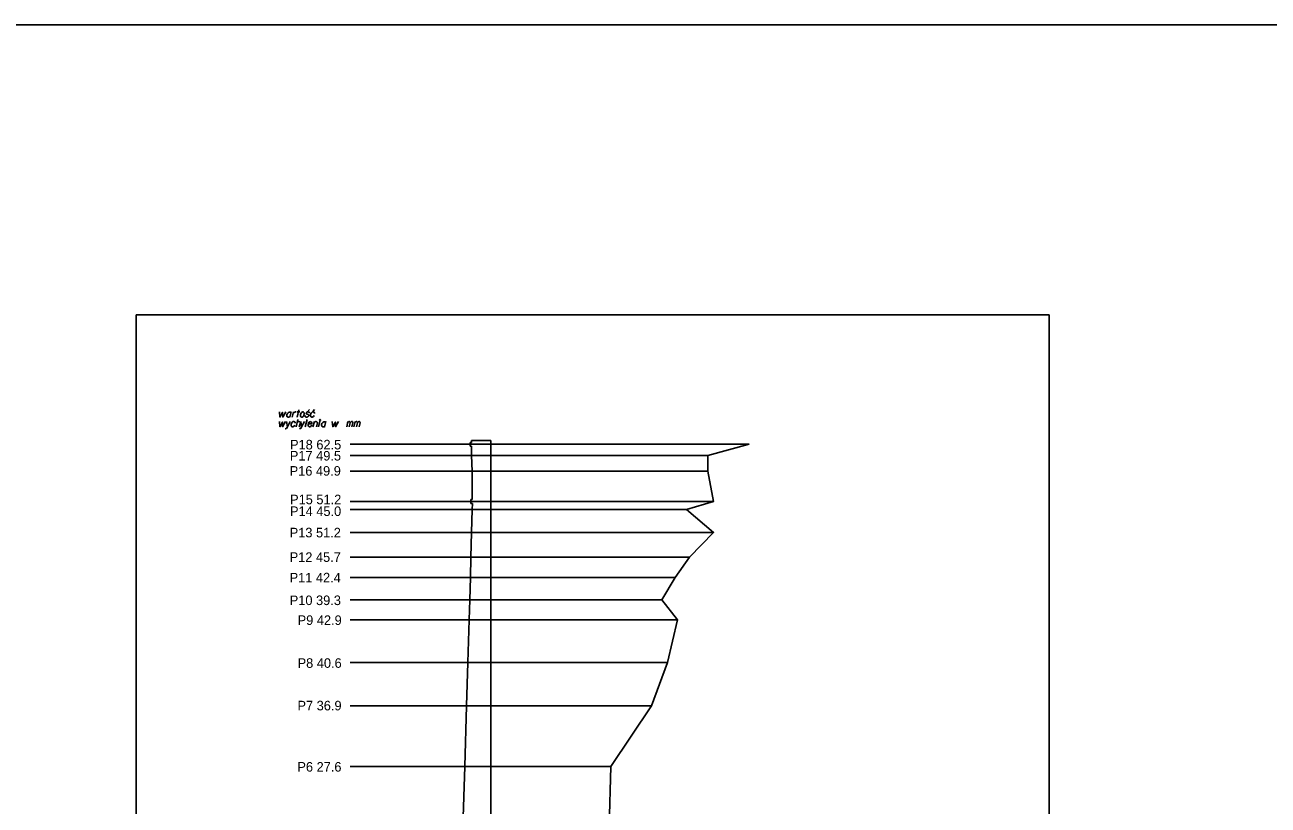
# Model space of a CAD drawing. Extents: x 138 to 264, y -75 to 121.
# Drawn here: x 166.54 to 195.15, y 20.71 to 38.66 of the extents above; entities that cross this region are included whole.
import ezdxf

# ---------------------------------------------------------------- set-up
doc = ezdxf.new("R2010")
doc.units = 0
for name, color, linetype in [('15 listopad 2008', 7, 'Continuous'), ('Ramka do drukowania', 7, 'Continuous'), ('Standart wykresów', 7, 'Continuous'), ('Wykresy 4 maj 2008', 7, 'Continuous')]:
    doc.layers.add(name, color=color, linetype=linetype)

msp = doc.modelspace()

# ---------------------------------------------------------------- linework, layer by layer
at = {"layer": '15 listopad 2008'}
msp.add_lwpolyline([(137.936, 38.661), (264.389, 38.661), (264.389, -75.347), (137.936, -75.347)], close=True, dxfattribs=at)
msp.add_lwpolyline([(177.265, 13.297), (177.835, 14.742), (178.265, 16.118), (178.825, 17.485), (179.085, 18.843), (179.985, 20.202), (180.025, 21.593), (180.955, 22.995), (181.325, 23.989), (181.555, 24.969), (181.195, 25.428), (181.505, 25.945), (181.835, 26.413), (182.385, 26.981), (181.765, 27.507), (182.385, 27.694), (182.255, 28.392), (182.255, 28.755), (183.205, 29.012)], dxfattribs=at)
at = {"layer": 'Ramka do drukowania'}
for p, q in [((169.105, 2.285), (169.105, 31.985)), ((169.105, 31.985), (190.105, 31.985)), ((190.105, 2.285), (190.105, 31.985))]:
    msp.add_line(p, q, dxfattribs=at)
at = {"layer": 'Standart wykresów'}
for p, q in [((177.265, 29.011), (174.028, 29.011)), ((176.783, 29.053), (176.783, 29.011)), ((176.82, 29.053), (176.783, 29.053)), ((176.783, 29.011), (176.783, 28.969)), ((176.82, 28.969), (176.783, 28.969)), ((176.82, 29.095), (176.82, 29.053)), ((176.82, 29.095), (177.265, 29.095)), ((176.82, 28.755), (176.82, 28.969)), ((177.265, 9.011), (177.265, 29.095)), ((177.265, 28.755), (174.028, 28.755)), ((176.835, 28.392), (176.82, 28.755)), ((177.265, 28.392), (174.028, 28.392)), ((176.835, 28.392), (176.835, 27.738)), ((177.265, 27.694), (174.028, 27.694)), ((177.265, 27.507), (174.028, 27.507)), ((176.805, 27.738), (176.805, 27.694)), ((176.805, 27.738), (176.835, 27.738)), ((176.805, 27.694), (176.805, 27.65)), ((176.839, 27.65), (176.805, 27.65)), ((176.82, 26.981), (176.835, 27.507)), ((176.835, 27.507), (176.839, 27.65)), ((177.265, 26.981), (174.028, 26.981)), ((176.805, 26.413), (176.82, 26.981)), ((177.265, 26.413), (174.028, 26.413)), ((176.79, 25.945), (176.805, 26.413)), ((177.265, 25.945), (174.028, 25.945)), ((176.778, 25.428), (176.79, 25.945)), ((177.265, 25.428), (174.028, 25.428)), ((176.76, 24.969), (176.778, 25.428)), ((177.265, 24.969), (174.028, 24.969)), ((176.733, 23.989), (176.76, 24.969)), ((177.265, 23.989), (174.028, 23.989)), ((176.703, 22.995), (176.733, 23.989)), ((177.265, 22.995), (174.028, 22.995)), ((176.663, 21.593), (176.703, 22.995)), ((177.265, 21.593), (174.028, 21.593)), ((176.618, 20.202), (176.663, 21.593))]:
    msp.add_line(p, q, dxfattribs=at)
for points in [[(172.399, 29.754), (172.409, 29.635), (172.472, 29.744), (172.473, 29.635), (172.543, 29.757)], [(172.663, 29.745), (172.654, 29.751), (172.632, 29.751), (172.618, 29.749), (172.595, 29.736), (172.575, 29.712), (172.566, 29.687), (172.565, 29.674), (172.566, 29.664), (172.57, 29.655), (172.578, 29.644), (172.587, 29.638), (172.601, 29.635), (172.612, 29.636), (172.622, 29.638), (172.637, 29.645)], [(172.666, 29.755), (172.634, 29.635)], [(172.688, 29.635), (172.721, 29.759)], [(172.713, 29.729), (172.719, 29.734), (172.734, 29.745), (172.749, 29.751), (172.761, 29.755), (172.779, 29.759)], [(172.802, 29.635), (172.845, 29.801)], [(172.802, 29.755), (172.864, 29.755)], [(172.934, 29.755), (172.943, 29.755), (172.953, 29.75), (172.964, 29.736), (172.965, 29.729), (172.966, 29.723), (172.966, 29.717), (172.966, 29.698), (172.963, 29.685), (172.956, 29.669), (172.948, 29.656), (172.935, 29.644), (172.923, 29.635), (172.904, 29.635), (172.896, 29.638), (172.888, 29.644), (172.884, 29.651), (172.879, 29.666), (172.879, 29.69), (172.881, 29.698), (172.887, 29.715), (172.892, 29.724), (172.894, 29.729), (172.908, 29.744), (172.921, 29.751), (172.934, 29.755)], [(173.089, 29.736), (173.086, 29.745), (173.076, 29.751), (173.069, 29.754), (173.057, 29.755), (173.046, 29.754), (173.031, 29.746), (173.02, 29.736), (173.016, 29.727), (173.015, 29.716), (173.017, 29.71), (173.023, 29.706), (173.025, 29.704), (173.033, 29.702), (173.042, 29.7), (173.055, 29.698), (173.063, 29.695), (173.07, 29.687), (173.072, 29.678), (173.071, 29.666), (173.066, 29.656), (173.055, 29.644), (173.046, 29.639), (173.036, 29.636), (173.023, 29.635), (173.007, 29.636), (172.997, 29.642), (172.991, 29.648), (172.989, 29.657), (172.989, 29.666), (172.993, 29.674)], [(173.089, 29.813), (173.057, 29.776)], [(173.205, 29.72), (173.203, 29.736), (173.197, 29.746), (173.189, 29.751), (173.173, 29.754), (173.159, 29.754), (173.14, 29.742), (173.126, 29.723), (173.116, 29.703), (173.112, 29.689), (173.112, 29.666), (173.113, 29.659), (173.118, 29.648), (173.13, 29.638), (173.143, 29.635), (173.157, 29.636), (173.165, 29.639), (173.182, 29.651), (173.195, 29.673)], [(173.206, 29.812), (173.173, 29.775)], [(172.397, 29.532), (172.408, 29.412), (172.471, 29.521), (172.472, 29.412), (172.541, 29.534)], [(172.647, 29.534), (172.581, 29.412), (172.56, 29.377), (172.554, 29.374), (172.548, 29.372), (172.535, 29.369), (172.53, 29.369)], [(172.564, 29.533), (172.581, 29.412)], [(172.759, 29.498), (172.757, 29.513), (172.751, 29.524), (172.743, 29.529), (172.727, 29.532), (172.713, 29.532), (172.694, 29.52), (172.68, 29.5), (172.67, 29.48), (172.666, 29.466), (172.666, 29.444), (172.667, 29.436), (172.672, 29.426), (172.684, 29.415), (172.697, 29.412), (172.711, 29.414), (172.719, 29.416), (172.736, 29.428), (172.749, 29.45)], [(172.781, 29.412), (172.824, 29.579)], [(172.806, 29.508), (172.81, 29.513), (172.815, 29.521), (172.819, 29.525), (172.821, 29.528), (172.825, 29.53), (172.829, 29.532), (172.833, 29.533), (172.837, 29.534), (172.846, 29.534), (172.853, 29.533), (172.861, 29.53), (172.866, 29.528), (172.87, 29.524), (172.874, 29.518), (172.876, 29.515), (172.878, 29.512), (172.88, 29.507), (172.88, 29.503), (172.855, 29.412)], [(172.974, 29.534), (172.908, 29.412), (172.887, 29.377), (172.882, 29.374), (172.875, 29.372), (172.862, 29.369), (172.857, 29.369)], [(172.891, 29.533), (172.908, 29.412)], [(172.993, 29.412), (173.036, 29.579)], [(173.062, 29.482), (173.146, 29.482), (173.147, 29.495), (173.145, 29.507), (173.139, 29.518), (173.124, 29.53), (173.111, 29.532), (173.1, 29.529), (173.086, 29.521), (173.077, 29.512), (173.069, 29.498), (173.063, 29.487), (173.058, 29.465), (173.058, 29.45), (173.06, 29.439), (173.063, 29.428), (173.079, 29.414), (173.09, 29.412), (173.1, 29.414), (173.101, 29.414), (173.118, 29.422), (173.128, 29.431), (173.131, 29.437), (173.133, 29.439), (173.139, 29.45)], [(173.169, 29.412), (173.202, 29.533)], [(173.194, 29.504), (173.198, 29.511), (173.203, 29.518), (173.207, 29.522), (173.213, 29.528), (173.218, 29.53), (173.224, 29.533), (173.231, 29.534), (173.236, 29.534), (173.243, 29.533), (173.248, 29.53), (173.253, 29.528), (173.258, 29.524), (173.264, 29.518), (173.266, 29.515), (173.269, 29.509), (173.271, 29.503), (173.248, 29.412)], [(173.294, 29.412), (173.328, 29.539)], [(173.33, 29.579), (173.337, 29.579), (173.341, 29.576), (173.345, 29.571), (173.345, 29.564), (173.341, 29.559), (173.337, 29.556), (173.33, 29.556), (173.326, 29.559), (173.322, 29.564), (173.322, 29.571), (173.326, 29.576), (173.33, 29.579)], [(173.465, 29.522), (173.456, 29.529), (173.434, 29.529), (173.421, 29.526), (173.397, 29.513), (173.377, 29.49), (173.368, 29.465), (173.367, 29.452), (173.368, 29.441), (173.372, 29.432), (173.38, 29.422), (173.389, 29.415), (173.404, 29.412), (173.414, 29.414), (173.425, 29.415), (173.439, 29.423)], [(173.468, 29.533), (173.436, 29.412)], [(173.613, 29.532), (173.623, 29.412), (173.686, 29.521), (173.688, 29.412), (173.757, 29.534)], [(173.945, 29.412), (173.975, 29.532)], [(173.968, 29.5), (173.974, 29.515), (173.981, 29.522), (173.989, 29.528), (173.996, 29.532), (174.002, 29.534), (174.009, 29.534), (174.012, 29.533), (174.017, 29.528), (174.023, 29.521), (174.026, 29.509), (174.028, 29.503), (174.034, 29.515), (174.042, 29.522), (174.05, 29.528), (174.058, 29.532), (174.064, 29.534), (174.071, 29.534), (174.076, 29.533), (174.08, 29.528), (174.084, 29.521), (174.088, 29.509), (174.089, 29.503), (174.067, 29.412)], [(174.006, 29.412), (174.028, 29.503)], [(174.111, 29.412), (174.142, 29.532)], [(174.134, 29.5), (174.14, 29.515), (174.147, 29.522), (174.155, 29.528), (174.163, 29.532), (174.168, 29.534), (174.176, 29.534), (174.178, 29.533), (174.183, 29.528), (174.189, 29.521), (174.193, 29.509), (174.194, 29.503), (174.2, 29.515), (174.208, 29.522), (174.216, 29.528), (174.224, 29.532), (174.231, 29.534), (174.237, 29.534), (174.242, 29.533), (174.246, 29.528), (174.25, 29.521), (174.254, 29.509), (174.255, 29.503), (174.233, 29.412)], [(174.172, 29.412), (174.194, 29.503)]]:
    msp.add_lwpolyline(points, dxfattribs=at)
at = {"layer": 'Wykresy 4 maj 2008'}
for p, q in [((177.265, 29.011), (183.203, 29.011)), ((177.265, 28.755), (182.255, 28.755)), ((177.265, 28.392), (182.255, 28.392)), ((177.265, 27.694), (182.385, 27.694)), ((177.265, 27.507), (181.765, 27.507)), ((177.265, 26.981), (182.385, 26.981)), ((177.265, 26.413), (181.835, 26.413)), ((177.265, 25.945), (181.505, 25.945)), ((177.265, 25.428), (181.195, 25.428)), ((177.265, 24.969), (181.555, 24.969)), ((177.265, 23.989), (181.325, 23.989)), ((177.265, 22.995), (180.955, 22.995)), ((177.265, 21.593), (180.025, 21.593))]:
    msp.add_line(p, q, dxfattribs=at)

# ---------------------------------------------------------------- texts
for s, p in [('P18 62.5', (172.642, 28.892)), ('P17 49.5', (172.637, 28.636)), ('P16 49.9', (172.633, 28.287)), ('P15 51.2', (172.643, 27.63)), ('P14 45.0', (172.641, 27.36)), ('P13 51.2', (172.634, 26.868)), ('P12 45.7', (172.633, 26.304)), ('P11 42.4', (172.632, 25.832)), ('P10 39.3', (172.635, 25.31)), ('P9 42.9', (172.817, 24.853)), ('P8 40.6', (172.816, 23.866)), ('P7 36.9', (172.813, 22.887)), ('P6 27.6', (172.811, 21.478))]:
    msp.add_text(s, height=0.22, dxfattribs=at).set_placement(p)

doc.saveas('drawing.dxf')
